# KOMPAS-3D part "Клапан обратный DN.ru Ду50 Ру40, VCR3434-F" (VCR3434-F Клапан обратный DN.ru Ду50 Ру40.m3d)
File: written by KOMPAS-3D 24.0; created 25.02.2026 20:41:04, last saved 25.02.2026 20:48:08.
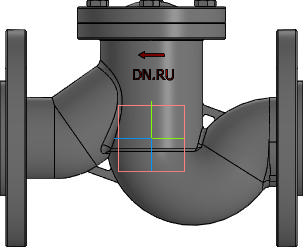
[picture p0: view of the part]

Document properties: Автор: R2D2; Полное имя файла: VCR3434-F Клапан обратный DN.ru Ду50 Ру40.cdw

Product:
- Part/product: Клапан обратный DN.ru Ду50 Ру40  | designation VCR3434-F
    Масса: 11.2
    Раздел спецификации: Прочие изделия
    Форматы листов документа: A2
    Примечание: D100-04055
    additional columns: D100-04055

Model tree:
1. Операция без истории:1

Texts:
  VCR3434-F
